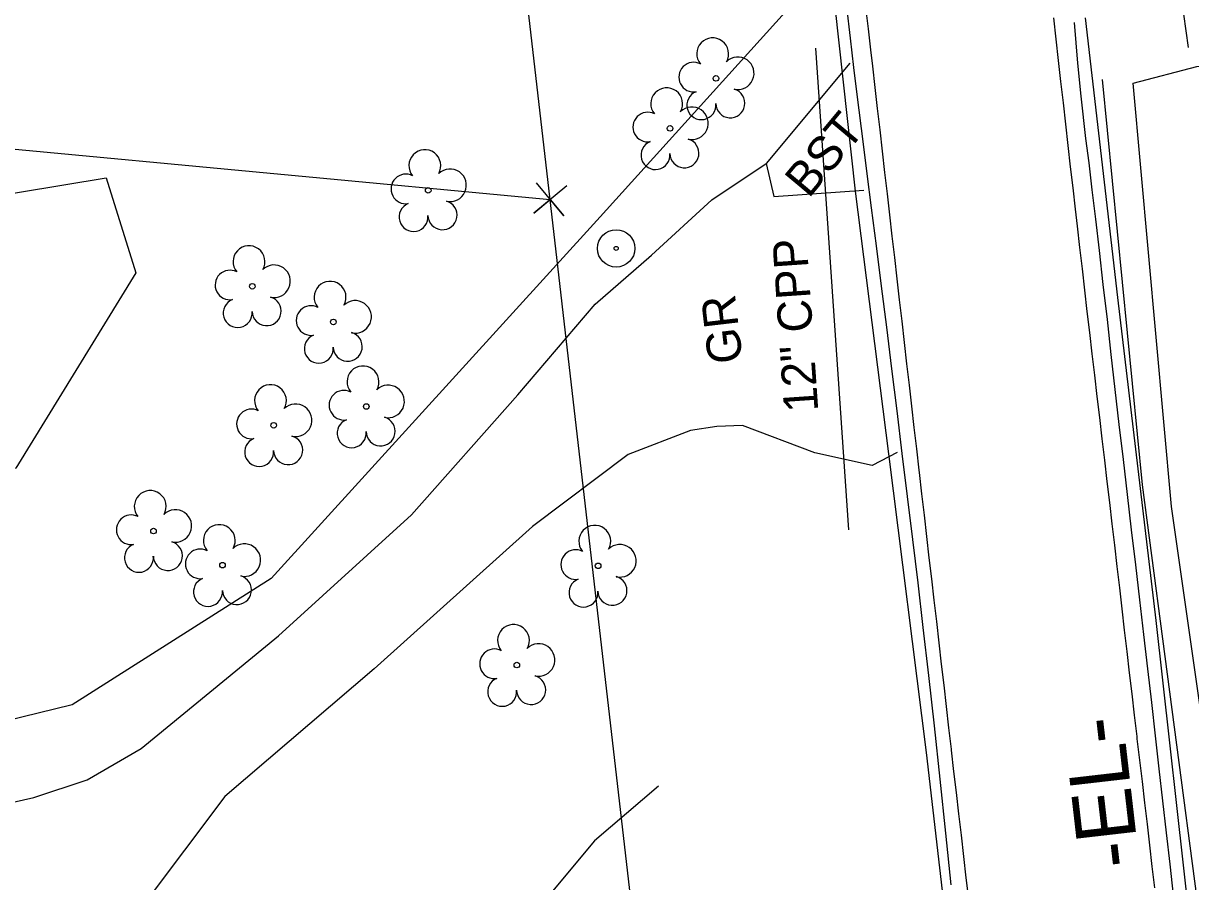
# Model space of a CAD drawing. Extents: x 472260 to 482161, y 489063 to 507124.
# Drawn here: x 478087.6 to 478223.9, y 496781 to 496881.2 of the extents above; entities that cross this region are included whole.
import ezdxf

# ---------------------------------------------------------------- set-up
doc = ezdxf.new("R2010")
doc.units = 0
for name, color, linetype in [('Exist Roads Change in Surface', 7, 'Continuous'), ('Exist Roads EOP Other Cogo Point CELL', 7, 'Continuous'), ('Exist Structure Minor Drop Inlet Cogo Elevation', 7, 'Continuous'), ('Exist Structure Minor Drop Inlet Cogo Number', 7, 'Continuous'), ('Exist Structure Minor Pipes RCP 18 Inch', 7, 'Continuous'), ('Exist Utilities Water Meter CELL', 7, 'Continuous'), ('Prop Drainage Structure Catch Basin Convert From Junction Box Label', 7, 'Continuous'), ('Prop Drainage Structure Drop Inlet Grate 2 Narrow Slots and Sag Grates 840 24 CELL', 7, 'Continuous'), ('Prop Drainage Structure Drop Inlet Grate 2 Wide Slots and Flat Grates 840 20 Label', 7, 'Continuous'), ('Prop Drainage Structure Pipe Collar CELL', 7, 'Continuous'), ('Prop Drainage Structure Pipe CSP 24in Label', 7, 'Continuous'), ('Prop Drainage Structure Pipe RCP 18in Class III', 7, 'Continuous'), ('Prop Drainage Structure Pipe RCP 66in Class IV', 7, 'Continuous'), ('Prop Drainage Structure Pipe Stub Out CELL', 7, 'Continuous'), ('Prop Drainage Structure Plot Symbol 20 Scale CELL', 7, 'Continuous'), ('Prop Drainage Structure Plot Symbol 50 Scale CELL', 7, 'Continuous'), ('Prop Drainage Structure Tops and Inverts LABEL', 7, 'Continuous'), ('Prop Earthen Structure Ditch Flow Line', 7, 'Continuous'), ('Prop Earthen Structure False Sump Label', 7, 'Continuous'), ('Prop Erosion Rip Rap Pad at Outlet Label', 7, 'Continuous')]:
    doc.layers.add(name, color=color, linetype=linetype)

msp = doc.modelspace()

# ---------------------------------------------------------------- linework, layer by layer
at = {"layer": 'Exist Roads EOP Other Cogo Point CELL'}
msp.add_line((478149.15, 496860.61), (478149.15, 496860.61), dxfattribs=at)
msp.add_lwpolyline([(478151.08, 496862.2), (478147.23, 496859.01), (478149.15, 496860.61), (478150.75, 496858.68), (478147.56, 496862.53)], dxfattribs=at)
at = {"layer": 'Exist Structure Minor Drop Inlet Cogo Elevation'}
msp.add_line((478244.7, 496030.8), (478097.62, 497308.11), dxfattribs=at)
at = {"layer": 'Exist Structure Minor Drop Inlet Cogo Number'}
msp.add_line((477960.57, 496878.27), (478149.15, 496860.61), dxfattribs=at)
at = {"layer": 'Exist Utilities Water Meter CELL'}
msp.add_lwpolyline([(478161.81, 496792.11), (478154.3, 496785.76), (478146.3, 496776.12), (478133.55, 496763.38), (478121.59, 496750.34), (478110.85, 496738.1), (478115.69, 496734.44), (478128.34, 496726.6), (478139.52, 496720.15), (478152.67, 496710.82), (478167.97, 496700.82), (478174.64, 496696.88)], dxfattribs=at)
at = {"layer": 'Prop Drainage Structure Catch Basin Convert From Junction Box Label'}
for points in [[(478184.79, 496861.57), (478179.12, 496913.19), (478176.06, 496939.31)], [(478237.35, 496653.47), (478235.03, 496674.28), (478232.01, 496703.74), (478227.66, 496741.94), (478223.91, 496775.59), (478219.91, 496811.48), (478215.43, 496849.16), (478211.66, 496881.8)], [(478209.7, 496647.59), (478206.64, 496669.29), (478205.56, 496679.82), (478204.9, 496690.6), (478200.79, 496727.33), (478197.78, 496755.66), (478193.1, 496796.07), (478188.68, 496830.93), (478184.79, 496861.57)]]:
    msp.add_lwpolyline(points, dxfattribs=at)
at = {"layer": 'Prop Drainage Structure Drop Inlet Grate 2 Narrow Slots and Sag Grates 840 24 CELL'}
for points in [[(478198.02, 496778.96), (478197.73, 496781.44), (478197.45, 496783.92), (478197.16, 496786.4), (478196.87, 496788.88), (478196.59, 496791.37), (478196.3, 496793.85), (478196.01, 496796.33), (478196, 496796.46), (478195.71, 496798.94), (478195.43, 496801.42), (478195.14, 496803.9), (478194.85, 496806.38), (478194.56, 496808.87), (478194.28, 496811.35), (478193.99, 496813.83), (478193.7, 496816.31), (478193.42, 496818.79), (478193.13, 496821.27), (478192.84, 496823.75), (478192.56, 496826.24), (478192.27, 496828.72), (478192.23, 496829.02), (478191.95, 496831.5), (478191.66, 496833.98), (478191.38, 496836.46), (478191.09, 496838.94), (478190.81, 496841.42), (478190.52, 496843.9), (478190.23, 496846.39), (478189.95, 496848.87), (478189.66, 496851.35), (478189.38, 496853.83), (478189.09, 496856.31), (478188.81, 496858.79), (478188.52, 496861.27), (478188.23, 496863.76), (478187.95, 496866.24), (478187.66, 496868.72), (478187.38, 496871.2), (478187.09, 496873.68), (478186.81, 496876.16), (478186.59, 496878.05), (478186.3, 496880.53), (478186.02, 496883.01)], [(478207.91, 496881.8), (478208.19, 496879.31), (478208.47, 496876.83), (478208.75, 496874.35), (478209.04, 496871.87), (478209.32, 496869.39), (478209.6, 496866.9), (478209.88, 496864.42), (478210.16, 496861.94), (478210.44, 496859.46), (478210.67, 496857.47), (478210.96, 496854.99), (478211.25, 496852.51), (478211.54, 496850.03), (478211.83, 496847.54), (478212.12, 496845.06), (478212.41, 496842.58), (478212.7, 496840.1), (478212.99, 496837.62), (478213.28, 496835.14), (478213.57, 496832.66), (478213.86, 496830.18), (478214.16, 496827.7), (478214.45, 496825.22), (478214.74, 496822.74), (478215.03, 496820.25), (478215.32, 496817.77), (478215.61, 496815.29), (478215.9, 496812.81), (478216.19, 496810.33), (478216.48, 496807.85), (478216.77, 496805.37), (478217.06, 496802.89), (478217.35, 496800.41), (478217.64, 496797.93), (478217.67, 496797.64), (478217.96, 496795.15), (478218.26, 496792.67), (478218.55, 496790.19), (478218.84, 496787.71), (478219.13, 496785.23), (478219.42, 496782.75), (478219.71, 496780.27)]]:
    msp.add_lwpolyline(points, dxfattribs=at)
at = {"layer": 'Prop Drainage Structure Drop Inlet Grate 2 Wide Slots and Flat Grates 840 20 Label'}
for p, q in [((478168.5, 496874.73), (478168.5, 496874.73)), ((478163.14, 496868.9), (478163.14, 496868.9)), ((478134.9, 496861.67), (478134.9, 496861.67)), ((478114.36, 496850.47), (478114.36, 496850.47)), ((478123.83, 496846.31), (478123.83, 496846.31)), ((478127.67, 496836.44), (478127.67, 496836.44)), ((478116.86, 496834.25), (478116.86, 496834.25)), ((478102.82, 496821.9), (478102.82, 496821.9)), ((478110.88, 496817.92), (478110.88, 496817.92)), ((478154.74, 496817.84), (478154.74, 496817.84)), ((478145.25, 496806.26), (478145.25, 496806.26))]:
    msp.add_line(p, q, dxfattribs=at)
for centre in [(478168.5, 496874.73), (478163.14, 496868.9), (478134.9, 496861.67), (478114.36, 496850.47), (478123.83, 496846.31), (478127.67, 496836.44), (478116.86, 496834.25), (478102.82, 496821.9), (478110.88, 496817.92), (478154.74, 496817.84), (478145.25, 496806.26)]:
    msp.add_circle(centre, 0.326, dxfattribs=at)
for centre, radius, start, end in [((478168.12, 496877.6), 1.86, 330.1651, 219.7134), ((478165.9, 496874.88), 1.73, 62.6636, 279.3457), ((478171.05, 496875.32), 1.9, 257.1011, 134.1999), ((478162.75, 496871.77), 1.86, 330.1651, 219.7134), ((478166.8, 496871.61), 1.69, 111.5671, 6.231), ((478170.18, 496871.83), 1.7, 181.2822, 74.56), ((478165.69, 496869.49), 1.9, 257.1011, 134.1999), ((478160.53, 496869.05), 1.73, 62.6636, 279.3457), ((478161.44, 496865.78), 1.69, 111.5671, 6.231), ((478164.81, 496866), 1.7, 181.2822, 74.56), ((478134.51, 496864.55), 1.86, 330.1651, 219.7134), ((478132.29, 496861.83), 1.73, 62.6636, 279.3457), ((478137.45, 496862.26), 1.9, 257.1011, 134.1999), ((478136.57, 496858.77), 1.7, 181.2822, 74.56), ((478133.19, 496858.55), 1.69, 111.5671, 6.231), ((478113.97, 496853.34), 1.86, 330.1651, 219.7134), ((478111.75, 496850.62), 1.73, 62.6636, 279.3457), ((478116.9, 496851.06), 1.9, 257.1011, 134.1999), ((478123.44, 496849.19), 1.86, 330.1651, 219.7134), ((478112.65, 496847.35), 1.69, 111.5671, 6.231), ((478116.03, 496847.57), 1.7, 181.2822, 74.56), ((478121.22, 496846.47), 1.73, 62.6636, 279.3457), ((478126.37, 496846.9), 1.9, 257.1011, 134.1999), ((478122.12, 496843.19), 1.69, 111.5671, 6.231), ((478125.5, 496843.42), 1.7, 181.2822, 74.56), ((478127.28, 496839.31), 1.86, 330.1651, 219.7134), ((478116.48, 496837.12), 1.86, 330.1651, 219.7134), ((478130.22, 496837.03), 1.9, 257.1011, 134.1999), ((478125.06, 496836.59), 1.73, 62.6636, 279.3457), ((478114.26, 496834.4), 1.73, 62.6636, 279.3457), ((478119.41, 496834.83), 1.9, 257.1011, 134.1999), ((478125.96, 496833.32), 1.69, 111.5671, 6.231), ((478129.34, 496833.54), 1.7, 181.2822, 74.56), ((478118.54, 496831.35), 1.7, 181.2822, 74.56), ((478115.16, 496831.13), 1.69, 111.5671, 6.231), ((478102.44, 496824.77), 1.86, 330.1651, 219.7134), ((478100.22, 496822.05), 1.73, 62.6636, 279.3457), ((478105.37, 496822.49), 1.9, 257.1011, 134.1999), ((478110.5, 496820.79), 1.86, 330.1651, 219.7134), ((478154.35, 496820.71), 1.86, 330.1651, 219.7134), ((478101.12, 496818.78), 1.69, 111.5671, 6.231), ((478104.5, 496819), 1.7, 181.2822, 74.56), ((478108.28, 496818.07), 1.73, 62.6636, 279.3457), ((478113.43, 496818.51), 1.9, 257.1011, 134.1999), ((478152.13, 496817.99), 1.73, 62.6636, 279.3457), ((478157.29, 496818.43), 1.9, 257.1011, 134.1999), ((478112.56, 496815.02), 1.7, 181.2822, 74.56), ((478109.18, 496814.8), 1.69, 111.5671, 6.231), ((478153.03, 496814.72), 1.69, 111.5671, 6.231), ((478156.41, 496814.94), 1.7, 181.2822, 74.56), ((478144.86, 496809.13), 1.86, 330.1651, 219.7134), ((478147.79, 496806.85), 1.9, 257.1011, 134.1999), ((478142.64, 496806.41), 1.73, 62.6636, 279.3457), ((478143.54, 496803.14), 1.69, 111.5671, 6.231), ((478146.92, 496803.36), 1.7, 181.2822, 74.56)]:
    msp.add_arc(centre, radius, start, end, dxfattribs=at)
at = {"layer": 'Prop Drainage Structure Pipe CSP 24in Label'}
msp.add_line((478184.01, 496822.06), (478180.16, 496878.27), dxfattribs=at)
at = {"layer": 'Prop Drainage Structure Pipe RCP 18in Class III'}
for points in [[(478037.57, 496786.31), (478037.21, 496790.3), (478049.62, 496790.31), (478066.4, 496789.43), (478074.23, 496789.38), (478082.07, 496789.29), (478088.83, 496790.79), (478095.08, 496792.85), (478101.38, 496796.51), (478117.42, 496809.66), (478132.93, 496823.81), (478145.35, 496837.79), (478154.39, 496848.37), (478160.97, 496854.11), (478168.04, 496860.56), (478174.37, 496864.8)], [(478189.67, 496831.06), (478186.75, 496829.54), (478180.04, 496831.02), (478171.59, 496834.23), (478168.6, 496834.12), (478165.53, 496833.64), (478158.26, 496830.84), (478147.06, 496822.45), (478128.57, 496805.81), (478111.16, 496790.92), (478101.72, 496778.39), (478096.6, 496766.23)]]:
    msp.add_lwpolyline(points, dxfattribs=at)
at = {"layer": 'Prop Drainage Structure Pipe RCP 66in Class IV'}
msp.add_line((478218.07, 496918.75), (478223.65, 496878.34), dxfattribs=at)
at = {"layer": 'Prop Drainage Structure Pipe Stub Out CELL'}
for points in [[(478195.99, 496780.62), (478195.34, 496786.66), (478194.67, 496792.94), (478194.01, 496799.17), (478193.36, 496805.06), (478192.72, 496810.63), (478192.1, 496815.87), (478191.48, 496820.92), (478190.87, 496825.95), (478190.26, 496830.95), (478189.65, 496835.92), (478189.04, 496840.84), (478188.44, 496845.7), (478187.84, 496850.48), (478187.24, 496855.2), (478186.68, 496859.64), (478186.17, 496863.59), (478185.73, 496867.04), (478184.98, 496872.86), (478184.6, 496876), (478184.2, 496879.41), (478183.78, 496883.1)], [(478210.33, 496881.25), (478210.74, 496876.52), (478211.12, 496872.67), (478211.67, 496867.72), (478212.03, 496864.86), (478212.41, 496861.72), (478212.82, 496858.32), (478213.25, 496854.64), (478213.7, 496850.69), (478214.17, 496846.61), (478214.63, 496842.52), (478215.1, 496838.43), (478215.57, 496834.34), (478216.04, 496830.25), (478216.52, 496826.15), (478217, 496822.05), (478217.48, 496817.95), (478217.96, 496813.87), (478218.43, 496809.83), (478218.9, 496805.84), (478219.35, 496801.89), (478219.79, 496797.99), (478220.23, 496794.16), (478220.66, 496790.4), (478221.08, 496786.7), (478221.49, 496783.04), (478221.9, 496779.4)]]:
    msp.add_lwpolyline(points, dxfattribs=at)
at = {"layer": 'Prop Drainage Structure Plot Symbol 20 Scale CELL'}
for radius in [2.18, 0.24]:
    msp.add_circle((478156.85, 496854.89), radius, dxfattribs=at)
at = {"layer": 'Prop Drainage Structure Plot Symbol 50 Scale CELL'}
msp.add_lwpolyline([(478213.59, 496874.62), (478218.27, 496827.31), (478225.22, 496774.85), (478233.42, 496715.49), (478237.99, 496686.86), (478241.19, 496672.25), (478245.14, 496656.32)], dxfattribs=at)
at = {"layer": 'Prop Drainage Structure Tops and Inverts LABEL'}
for points in [[(478141.65, 497174.35), (478149.25, 497124.62), (478158.96, 497058.2), (478166.01, 496982.58), (478178.06, 496884.14), (478154.97, 496858.56), (478116.58, 496816.35), (478093.34, 496801.61), (478073.88, 496796.87), (478056.27, 496795.04), (478052.86, 496799.11), (478045.86, 496797.88)], [(478261.88, 496673.53), (478268.79, 496630.22), (478261.26, 496630.17), (478251.48, 496651.36), (478246, 496666.8), (478235.83, 496719.95), (478227.64, 496783.09), (478221.71, 496824.78), (478217.22, 496874.18), (478224.65, 496876.12), (478232.47, 496876.32), (478234.8, 496872.07), (478275.37, 496877.27), (478308.83, 496880.62), (478315.01, 496872.92), (478323.49, 496861.41), (478334.86, 496854.13), (478365.63, 496846.02)]]:
    msp.add_lwpolyline(points, dxfattribs=at)
at = {"layer": 'Prop Earthen Structure Ditch Flow Line'}
msp.add_lwpolyline([(478184.12, 496876.49), (478174.37, 496864.8), (478175.26, 496860.95), (478185.78, 496861.69)], dxfattribs=at)
at = {"layer": 'Prop Erosion Rip Rap Pad at Outlet Label'}
msp.add_lwpolyline([(478058.26, 496826.98), (478056.09, 496830.98), (478072.07, 496858.96), (478097.31, 496863.14), (478100.74, 496852.05), (478086.76, 496829.23), (478071.88, 496827.58), (478066.41, 496820.6), (478058.26, 496826.98)], dxfattribs=at)

# ---------------------------------------------------------------- texts
at = {"layer": 'Exist Roads Change in Surface'}
msp.add_text('BST', height=4, rotation=50.1345, dxfattribs=at).set_placement((478179.33, 496860.63))
at = {"layer": 'Exist Structure Minor Pipes RCP 18 Inch'}
msp.add_text('12" CPP', height=4, rotation=93.9201, dxfattribs=at).set_placement((478180.46, 496835.9))
at = {"layer": 'Prop Drainage Structure Pipe Collar CELL'}
msp.add_text('-EL-', height=7, rotation=96.5685, dxfattribs=at).set_placement((478217.99, 496782.94))
at = {"layer": 'Prop Earthen Structure False Sump Label'}
msp.add_text('GR', height=4, rotation=96.6796, dxfattribs=at).set_placement((478171.64, 496841.68))

doc.saveas('drawing.dxf')
